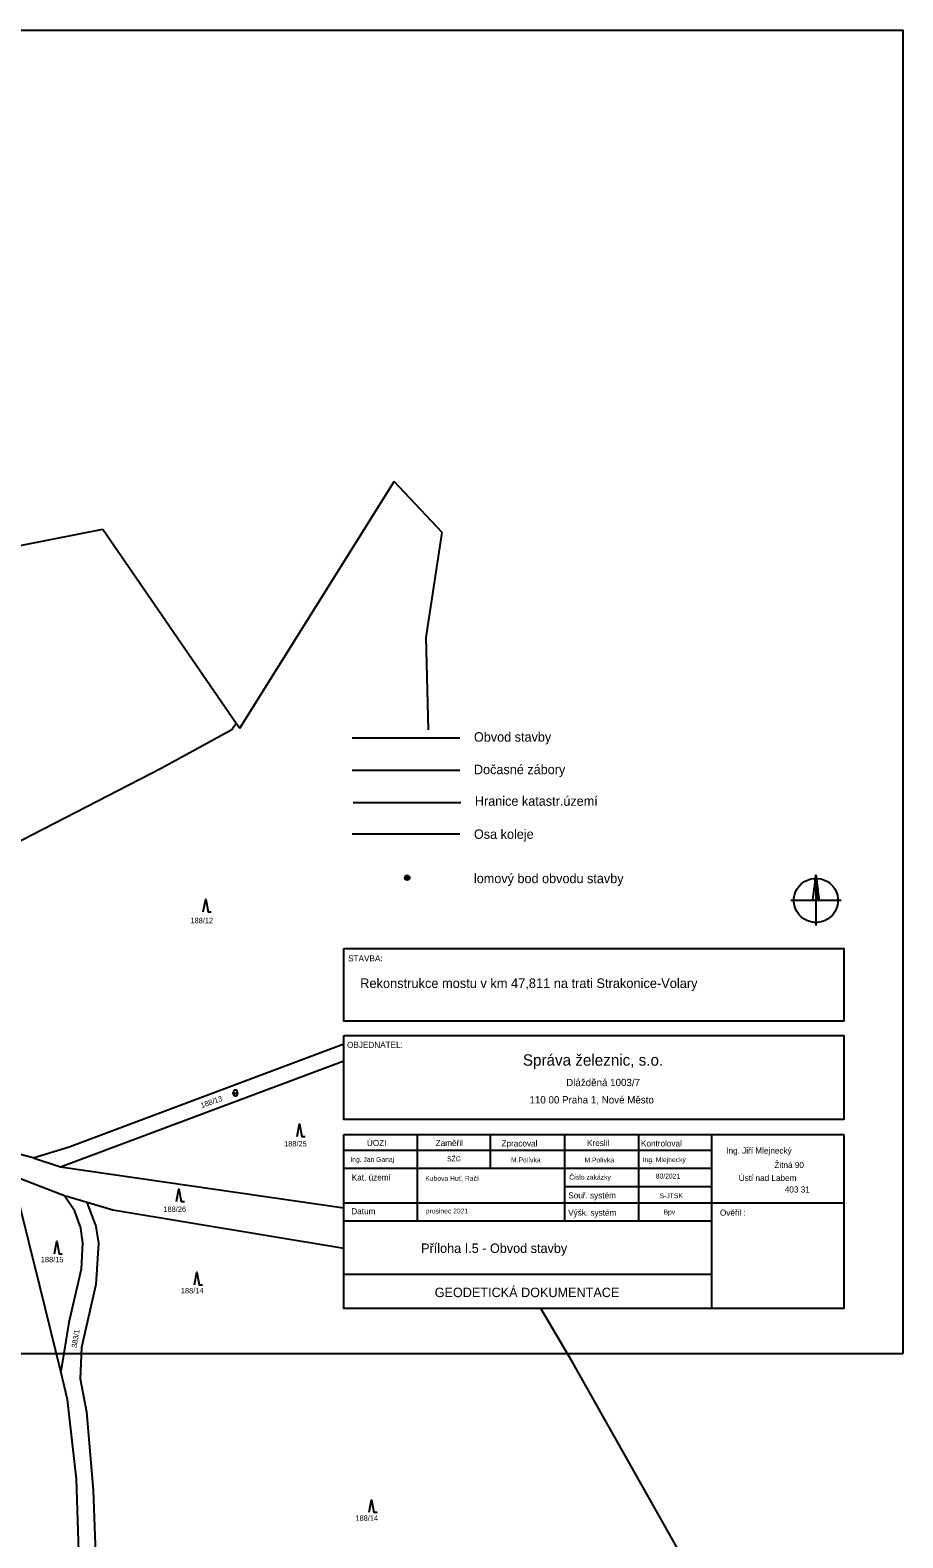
# Model space of a CAD drawing. Extents: x -811039 to -805820, y -1161436 to -1155864.
# Drawn here: x -806542 to -806265, y -1157727.6 to -1157249.3 of the extents above; entities that cross this region are included whole.
import ezdxf

# ---------------------------------------------------------------- set-up
doc = ezdxf.new("R2010")
doc.units = 0
for name, color, linetype in [('26 - obvod_stavby', 7, 'Continuous'), ('27 - dočasné zábory', 7, 'Continuous'), ('body', 7, 'Continuous'), ('Default', 7, 'Continuous'), ('KN_HRANICE', 7, 'Continuous'), ('KN_KULTURY', 7, 'Continuous'), ('KN_PARCELY', 7, 'Continuous'), ('kú', 7, 'Continuous'), ('LEGENDA', 7, 'Continuous'), ('tabulka', 7, 'Continuous'), ('Vrstva 1', 7, 'Continuous')]:
    doc.layers.add(name, color=color, linetype=linetype)

# ---------------------------------------------------------------- blocks, each defined once
blk = doc.blocks.new('308')
at = {"layer": 'Default'}
blk.add_lwpolyline([(-0.75, 0), (0, 4), (0.75, 0), (1.75, 0)], dxfattribs=at)
blk = doc.blocks.new('316')
at = {"layer": 'Default'}
for points in [[(-1, 1), (0.27, 1), (1, 1)], [(-0.5, 1.5), (-0.4, 1.79), (-0.15, 1.97), (0.16, 1.97), (0.41, 1.79), (0.51, 1.5), (0.51, 0.5), (0.41, 0.21), (0.16, 0.03), (-0.15, 0.03), (-0.4, 0.21), (-0.5, 0.5), (-0.5, 1.5)]]:
    blk.add_lwpolyline(points, dxfattribs=at)
blk = doc.blocks.new('SEVER')
at = {"layer": 'Default'}
for points in [[(5.5, 69.8), (16.3, 68.1), (26.7, 64.7), (36.5, 59.7), (45.4, 53.2), (53.2, 45.4), (59.7, 36.5), (64.7, 26.7), (68.1, 16.3), (69.8, 5.5), (69.8, -5.5), (68.1, -16.3), (64.7, -26.7), (59.7, -36.5), (53.2, -45.4), (45.4, -53.2), (36.5, -59.7), (26.7, -64.7), (16.3, -68.1), (5.5, -69.8), (-5.5, -69.8), (-16.3, -68.1), (-26.7, -64.7), (-36.5, -59.7), (-45.4, -53.2), (-53.2, -45.4), (-59.7, -36.5), (-64.7, -26.7), (-68.1, -16.3), (-69.8, -5.5), (-69.8, 5.5), (-68.1, 16.3), (-64.7, 26.7), (-59.7, 36.5), (-53.2, 45.4), (-45.4, 53.2), (-36.5, 59.7), (-26.7, 64.7), (-16.3, 68.1), (-5.5, 69.8), (5.5, 69.8)], [(-10, 0), (-8.5, 12), (-7, 24), (-5.5, 36), (-4, 48), (-2.5, 60), (-1, 72), (0, 80), (1.5, 68), (3, 56), (4.5, 44), (6, 32), (7.5, 20), (9, 8), (10, 0), (9.2, 0.8), (9.2, 5.6), (8.4, 12), (8.4, 0.8), (7.6, 0.8), (7.6, 13.5), (7.6, 18.4), (6.8, 24.8), (6.8, 12.1), (6.8, 0.8), (6, 0.8), (6, 13.5), (6, 26.2), (6, 31.2), (5.2, 36.8), (5.2, 24.1), (5.2, 11.4), (5.2, 0.8), (4.4, 0.8), (4.4, 13.5), (4.4, 26.2), (4.4, 38.9), (4.4, 43.2), (3.6, 50.4), (3.6, 37.7), (3.6, 25), (3.6, 12.3), (3.6, 0.8), (2.8, 0.8), (2.8, 13.5), (2.8, 26.2), (2.8, 38.9), (2.8, 51.6), (2.8, 56), (2, 63.2), (2, 50.5), (2, 37.8), (2, 25.1), (2, 12.4), (2, 0.8), (1.2, 0.8), (1.2, 13.5), (1.2, 26.2), (1.2, 38.9), (1.2, 51.6), (1.2, 64.3), (1.2, 69.6), (0.4, 76), (0.4, 63.3), (0.4, 50.6), (0.4, 37.9), (0.4, 25.2), (0.4, 12.5), (0.4, 0.8)], [(0, 80), (0, 67.3), (0, 54.6), (0, 41.9), (0, 29.2), (0, 16.5), (0, 3.8), (0, -8.9), (0, -21.6), (0, -34.3), (0, -47), (0, -59.7), (0, -72.4), (0, -80)], [(80, 0), (67.3, 0), (54.6, 0), (41.9, 0), (29.2, 0), (16.5, 0), (3.8, 0), (-8.9, 0), (-21.6, 0), (-34.3, 0), (-47, 0), (-59.7, 0), (-72.4, 0), (-80, 0)]]:
    blk.add_lwpolyline(points, dxfattribs=at)

msp = doc.modelspace()

# ---------------------------------------------------------------- linework, layer by layer
at = {"layer": '26 - obvod_stavby'}
msp.add_line((-806439.77, -1157473.77), (-806405.58, -1157473.77), dxfattribs=at)
at = {"layer": '27 - dočasné zábory'}
msp.add_line((-806439.77, -1157484.09), (-806405.58, -1157484.09), dxfattribs=at)
at = {"layer": 'body'}
for radius in [0.75, 0.35]:
    msp.add_circle((-806422.31, -1157518.22), radius, dxfattribs=at)
at = {"layer": 'KN_HRANICE'}
for p, q in [((-806500.38, -1157483.48), (-806478, -1157471.14)), ((-806478, -1157471.14), (-806476.59, -1157469.13)), ((-806551.31, -1157509.66), (-806500.38, -1157483.48)), ((-806529.68, -1157603.58), (-806442.41, -1157570.94)), ((-806532.39, -1157609.93), (-806442.41, -1157576.28)), ((-806541.05, -1157607.1), (-806552.56, -1157604.15)), ((-806541.05, -1157607.1), (-806529.68, -1157603.58)), ((-806541.05, -1157607.1), (-806532.39, -1157609.93)), ((-806531.09, -1157619.08), (-806549.56, -1157612.09)), ((-806532.39, -1157609.93), (-806442.41, -1157622.91)), ((-806539, -1157647.81), (-806545.82, -1157620.05)), ((-806523.89, -1157621.25), (-806531.09, -1157619.08)), ((-806527.85, -1157624.03), (-806531.09, -1157619.08)), ((-806515.8, -1157623.69), (-806523.89, -1157621.25)), ((-806521.27, -1157628.25), (-806523.89, -1157621.25)), ((-806526.18, -1157628.74), (-806527.85, -1157624.03)), ((-806442.41, -1157635.81), (-806515.8, -1157623.69)), ((-806526.18, -1157628.74), (-806525.38, -1157634.04)), ((-806521.27, -1157628.25), (-806520.31, -1157634.18)), ((-806525.38, -1157634.04), (-806525.88, -1157642.35)), ((-806520.31, -1157634.18), (-806521.19, -1157647.31)), ((-806525.88, -1157642.35), (-806529.79, -1157659.37)), ((-806532.33, -1157674.87), (-806539, -1157647.81)), ((-806521.19, -1157647.31), (-806525.69, -1157667.23)), ((-806369.85, -1157671.95), (-806379.9, -1157654.85)), ((-806529.79, -1157659.37), (-806532.33, -1157674.87)), ((-806525.69, -1157667.23), (-806526.2, -1157677.24)), ((-806334.8, -1157733.98), (-806369.85, -1157671.95)), ((-806530.15, -1157683.74), (-806532.33, -1157674.87)), ((-806526.2, -1157677.24), (-806524.15, -1157687.67)), ((-806527.36, -1157709), (-806530.15, -1157683.74)), ((-806524.15, -1157687.67), (-806522.05, -1157712.53)), ((-806526.14, -1157746.49), (-806527.36, -1157709)), ((-806522.05, -1157712.53), (-806520.82, -1157744.55))]:
    msp.add_line(p, q, dxfattribs=at)
at = {"layer": 'kú'}
for p, q in [((-806475.48, -1157470.74), (-806426.47, -1157392.43)), ((-806411.24, -1157408.67), (-806426.47, -1157392.43)), ((-806587.1, -1157421.03), (-806518.99, -1157407.63)), ((-806518.99, -1157407.63), (-806476.59, -1157469.13)), ((-806416.31, -1157441.98), (-806411.24, -1157408.67)), ((-806415.58, -1157471.3), (-806416.31, -1157441.98)), ((-806476.59, -1157469.13), (-806475.48, -1157470.74)), ((-806439.49, -1157494.28), (-806405.29, -1157494.28))]:
    msp.add_line(p, q, dxfattribs=at)
at = {"layer": 'LEGENDA'}
msp.add_lwpolyline([(-806264.96, -1157669.27), (-806858.96, -1157669.27), (-806858.96, -1157249.27), (-806264.96, -1157249.27)], close=True, dxfattribs=at)
at = {"layer": 'tabulka'}
for p, q in [((-806442.41, -1157599.72), (-806283.75, -1157599.72)), ((-806419.12, -1157599.72), (-806419.12, -1157627.04)), ((-806395.97, -1157599.72), (-806395.97, -1157610.34)), ((-806372.37, -1157599.72), (-806372.37, -1157627.04)), ((-806348.93, -1157599.72), (-806348.93, -1157627.04)), ((-806325.63, -1157654.85), (-806325.63, -1157599.72)), ((-806442.41, -1157604.63), (-806325.63, -1157604.63)), ((-806442.41, -1157610.34), (-806325.63, -1157610.34)), ((-806372.37, -1157616.15), (-806325.63, -1157616.15)), ((-806442.41, -1157621.34), (-806283.75, -1157621.34)), ((-806442.41, -1157627.04), (-806325.63, -1157627.04)), ((-806442.41, -1157644.03), (-806325.63, -1157644.03))]:
    msp.add_line(p, q, dxfattribs=at)
for points in [[(-806442.41, -1157540.64), (-806283.75, -1157540.64), (-806283.75, -1157563.7), (-806442.41, -1157563.7)], [(-806442.41, -1157568.22), (-806283.75, -1157568.22), (-806283.75, -1157594.91), (-806442.41, -1157594.91)]]:
    msp.add_lwpolyline(points, close=True, dxfattribs=at)
msp.add_lwpolyline([(-806283.75, -1157599.72), (-806283.75, -1157654.85), (-806442.41, -1157654.85), (-806442.41, -1157599.72)], dxfattribs=at)
at = {"layer": 'Vrstva 1'}
msp.add_line((-806439.77, -1157504.29), (-806405.58, -1157504.29), dxfattribs=at)

# ---------------------------------------------------------------- block references
at = {"layer": 'KN_KULTURY'}
for name, p in [('308', (-806486.3, -1157529.02)), ('316', (-806476.87, -1157587.52)), ('308', (-806456.48, -1157600.32)), ('308', (-806494.82, -1157620.9)), ('308', (-806533.58, -1157637.5)), ('308', (-806489.07, -1157647.38)), ('308', (-806433.65, -1157719.54))]:
    msp.add_blockref(name, p, dxfattribs=at)
at = {"layer": 'LEGENDA', "xscale": 0.1, "yscale": 0.10000000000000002}
msp.add_blockref('SEVER', (-806292.56, -1157525.39), dxfattribs=at)

# ---------------------------------------------------------------- texts
at = {"layer": 'KN_PARCELY'}
for s, p in [('188/12', (-806491.13, -1157532.62)), ('188/25', (-806461.4, -1157603.45)), ('188/26', (-806499.72, -1157624.23)), ('188/15', (-806538.64, -1157640.2)), ('188/14', (-806494.17, -1157650.08)), ('188/14', (-806438.75, -1157722.24))]:
    msp.add_text(s, height=1.7, dxfattribs=at).set_placement(p)
for s, rotation, p in [('188/13', 19.595, (-806487.58, -1157591.34)), ('383/1', 80.902, (-806527.24, -1157667.49))]:
    msp.add_text(s, height=1.7, rotation=rotation, dxfattribs=at).set_placement(p)
at = {"layer": 'LEGENDA'}
for s, p in [('Obvod stavby', (-806401.13, -1157475.02)), ('Dočasné zábory', (-806401.13, -1157485.35)), ('Hranice katastr.území', (-806400.84, -1157495.37)), ('Osa koleje', (-806401.13, -1157505.87)), ('lomový bod obvodu stavby', (-806401.13, -1157519.92))]:
    msp.add_text(s, height=3, dxfattribs=at).set_placement(p)
at = {"layer": 'tabulka'}
for s, height, p in [('STAVBA:', 1.94, (-806441.07, -1157544.74)), ('Rekonstrukce mostu v km 47,811 na trati Strakonice-Volary', 3.04, (-806437.25, -1157553.19)), ('OBJEDNATEL:', 1.94, (-806441.42, -1157572.2)), ('Správa železnic, s.o.', 3.61, (-806385.59, -1157577.84)), ('Dlážděná 1003/7', 2.32, (-806371.86, -1157584.33)), ('110 00 Praha 1, Nové Město', 2.32, (-806383.51, -1157589.82)), ('ÚOZI', 1.94, (-806435.11, -1157603.32)), ('Zaměřil', 1.94, (-806413.27, -1157603.32)), ('Zpracoval', 1.94, (-806392.38, -1157603.47)), ('Kreslil', 1.94, (-806365.22, -1157603.32)), ('Kontroloval', 1.94, (-806348.1, -1157603.47)), ('Ing. Jan Ganaj', 1.552, (-806440.4, -1157608.35)), ('SŽG', 1.552, (-806409.66, -1157608.18)), ('M.Polívka', 1.552, (-806389.37, -1157608.51)), ('M.Polívka', 1.552, (-806366.04, -1157608.54)), ('Ing. Mlejnecký', 1.552, (-806347.57, -1157608.42)), ('Ing. Jiří Mlejnecký', 1.94, (-806321.03, -1157605.73)), ('Kat. území', 1.94, (-806439.92, -1157614.27)), ('Číslo zakázky', 1.552, (-806370.9, -1157613.98)), ('80/2021', 1.552, (-806343.4, -1157613.65)), ('Ústí nad Labem', 1.94, (-806317.07, -1157614.42)), ('Žitná 90', 1.94, (-806305.74, -1157610.3)), ('Kubova Huť, Račí', 1.552, (-806416.58, -1157614.37)), ('403 31', 1.94, (-806302.44, -1157618.08)), ('Souř. systém', 1.94, (-806371.19, -1157619.95)), ('S-JTSK', 1.552, (-806342.2, -1157619.87)), ('Datum', 1.94, (-806440.06, -1157624.98)), ('prosinec 2021', 1.552, (-806416.43, -1157624.73)), ('Výšk. systém', 1.94, (-806371.21, -1157625.44)), ('Bpv', 1.552, (-806340.94, -1157625.05)), ('Ověřil :', 1.94, (-806323.03, -1157625.44)), ('Příloha I.5 - Obvod stavby', 3, (-806417.9, -1157637.25)), ('GEODETICKÁ DOKUMENTACE ', 3, (-806413.59, -1157651.27))]:
    msp.add_text(s, height=height, dxfattribs=at).set_placement(p)

doc.saveas('drawing.dxf')
